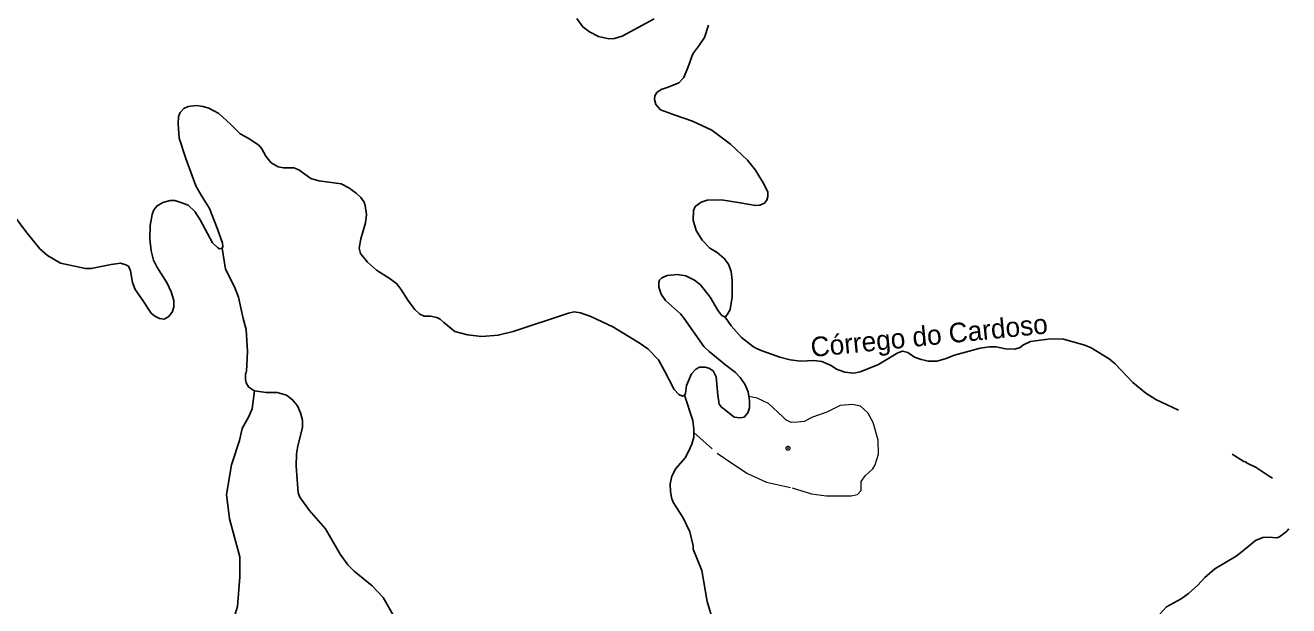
# Model space of a CAD drawing. Extents: x 396 to 422.2, y 7649.8 to 7677.6.
# Drawn here: x 403.57 to 408.72, y 7665.96 to 7668.32 of the extents above; entities that cross this region are included whole.
import ezdxf
from ezdxf.enums import TextEntityAlignment as Align

# ---------------------------------------------------------------- set-up
doc = ezdxf.new("R2010")
doc.units = 0
doc.header["$LTSCALE"] = 0.032
doc.header["$PDMODE"] = 32
doc.header["$PDSIZE"] = 0.016
doc.linetypes.add('SHORT_DASHED', pattern=[2.7, 1.5, -1.2])
for name, color, linetype, lineweight in [('2', 7, 'Continuous', 25), ('21', 7, 'SHORT_DASHED', 13), ('7', 7, 'Continuous', 25)]:
    doc.layers.add(name, color=color, linetype=linetype, lineweight=lineweight)
doc.layers.add('61', color=7, linetype='Continuous')

msp = doc.modelspace()

# ---------------------------------------------------------------- linework, layer by layer
at = {"layer": '2'}
for points in [[(405.8191, 7668.3498), (405.8427, 7668.3153), (405.8702, 7668.2957), (405.9066, 7668.276), (405.9489, 7668.2672), (405.9715, 7668.2681), (406.003, 7668.278), (406.1328, 7668.3478)], [(406.355, 7668.3222), (406.3383, 7668.2721), (406.3157, 7668.2377), (406.2911, 7668.2062), (406.2714, 7668.1531), (406.2537, 7668.1088), (406.234, 7668.0872), (406.1908, 7668.0695), (406.1613, 7668.0607), (406.1446, 7668.0479), (406.1357, 7668.0351), (406.1347, 7668.0204), (406.1396, 7667.9997), (406.1593, 7667.9781), (406.2183, 7667.9564), (406.2901, 7667.9309), (406.3688, 7667.8955), (406.4445, 7667.8384), (406.5133, 7667.7726), (406.5189, 7667.7656), (406.5467, 7667.7313), (406.5811, 7667.6742), (406.5959, 7667.6428), (406.5959, 7667.6251), (406.592, 7667.6093), (406.5821, 7667.5975), (406.5634, 7667.5897), (406.5457, 7667.5877), (406.4838, 7667.5995), (406.4081, 7667.6113), (406.3491, 7667.6093), (406.3245, 7667.6015), (406.3009, 7667.5838), (406.293, 7667.568), (406.2921, 7667.5287), (406.3039, 7667.4864), (406.3284, 7667.4471)], [(406.2576, 7666.8148), (406.2488, 7666.8119), (406.234, 7666.8178), (406.2144, 7666.8384), (406.176, 7666.9141), (406.1505, 7666.9594), (406.1082, 7667.0036), (406.0728, 7667.0292), (405.9646, 7667.0941), (405.8751, 7667.1364), (405.8329, 7667.1511), (405.8073, 7667.155), (405.7847, 7667.1501), (405.5595, 7667.0754), (405.4985, 7667.0597), (405.4317, 7667.0538), (405.3737, 7667.0607), (405.3215, 7667.0744), (405.2773, 7667.1108), (405.2616, 7667.1246), (405.2488, 7667.1324), (405.2222, 7667.1373), (405.1967, 7667.1373), (405.179, 7667.1452), (405.1583, 7667.1649), (405.1328, 7667.1983), (405.1023, 7667.2475), (405.0856, 7667.2691), (405.058, 7667.2888), (405.003, 7667.3252), (404.9656, 7667.3576), (404.9381, 7667.392), (404.9322, 7667.4146), (404.939, 7667.452), (404.9577, 7667.5179), (404.9626, 7667.5513), (404.9567, 7667.5877), (404.9518, 7667.6015), (404.939, 7667.6201), (404.9194, 7667.6388), (404.8899, 7667.6605), (404.8584, 7667.6762), (404.7984, 7667.6841), (404.7679, 7667.688), (404.7355, 7667.6978), (404.6863, 7667.7332), (404.6657, 7667.7411), (404.6411, 7667.7411), (404.6244, 7667.7411), (404.6028, 7667.745), (404.5742, 7667.7617), (404.5526, 7667.7883), (404.5359, 7667.8188), (404.5241, 7667.8335), (404.4798, 7667.862), (404.4474, 7667.8797), (404.4081, 7667.9191), (404.3599, 7667.9623), (404.3205, 7667.984), (404.2969, 7667.9918), (404.2694, 7667.9958), (404.236, 7667.9918), (404.2183, 7667.983), (404.2026, 7667.9663), (404.1967, 7667.9505), (404.1947, 7667.921), (404.1986, 7667.862), (404.2262, 7667.7794), (404.2665, 7667.6683), (404.2891, 7667.63), (404.3225, 7667.5759), (404.354, 7667.4953), (404.3756, 7667.4343), (404.3766, 7667.4205), (404.3741, 7667.4147)], [(404.3741, 7667.4147), (404.3628, 7667.4117), (404.3559, 7667.4156), (404.3353, 7667.4363), (404.2842, 7667.5297), (404.2625, 7667.5631), (404.236, 7667.5887), (404.2094, 7667.5995), (404.1809, 7667.6083), (404.1622, 7667.6083), (404.1327, 7667.6005), (404.1091, 7667.5867), (404.0964, 7667.571), (404.0885, 7667.5513), (404.0816, 7667.5061), (404.0796, 7667.451), (404.0855, 7667.4028), (404.0944, 7667.3655), (404.1082, 7667.3379), (404.1495, 7667.2711), (404.1662, 7667.2357), (404.177, 7667.2013), (404.177, 7667.1747), (404.1721, 7667.156), (404.1563, 7667.1354), (404.1377, 7667.1256), (404.119, 7667.1275), (404.1003, 7667.1373), (404.0846, 7667.1491), (404.0462, 7667.2091), (404.0197, 7667.2465), (404.0088, 7667.274), (404.001, 7667.3222), (403.9921, 7667.3409), (403.9823, 7667.3468), (403.9597, 7667.3527), (403.9223, 7667.3478), (403.8407, 7667.3311), (403.8181, 7667.3311), (403.7158, 7667.3527), (403.6627, 7667.3842), (403.6322, 7667.4117), (403.5742, 7667.4815), (403.5192, 7667.5572)], [(406.3284, 7667.4471), (406.3599, 7667.4137), (406.3894, 7667.396), (406.4189, 7667.3724), (406.4366, 7667.3488), (406.4474, 7667.3193)], [(406.4223, 7667.1333), (406.4091, 7667.1393), (406.3943, 7667.159), (406.3619, 7667.215), (406.3216, 7667.2642), (406.297, 7667.2839), (406.2626, 7667.3016), (406.2291, 7667.3075), (406.1859, 7667.3035), (406.1642, 7667.2937), (406.1554, 7667.2839), (406.1524, 7667.276), (406.1524, 7667.2553), (406.1623, 7667.2268), (406.18, 7667.2013), (406.2409, 7667.1472), (406.2557, 7667.1275), (406.3353, 7667.0135), (406.3579, 7666.9928), (406.4248, 7666.9377), (406.4651, 7666.9082), (406.4838, 7666.8876), (406.5025, 7666.8601), (406.5162, 7666.8296), (406.5189, 7666.8102)], [(406.4474, 7667.3193), (406.4504, 7667.2819), (406.4504, 7667.216), (406.4435, 7667.1649), (406.4327, 7667.1452), (406.4223, 7667.1333)], [(406.5189, 7666.8102), (406.5212, 7666.7942), (406.5221, 7666.7637), (406.5143, 7666.744), (406.5005, 7666.7253), (406.4828, 7666.7234), (406.4592, 7666.7263), (406.4376, 7666.743), (406.4179, 7666.7588), (406.4071, 7666.7666), (406.3983, 7666.7794), (406.3924, 7666.8158), (406.3865, 7666.8896), (406.3737, 7666.9141), (406.356, 7666.925), (406.3412, 7666.9289), (406.3186, 7666.9289), (406.3029, 7666.922), (406.2852, 7666.9023), (406.2645, 7666.8542), (406.2606, 7666.8217), (406.2576, 7666.8148)]]:
    msp.add_lwpolyline(points, dxfattribs=at)
at = {"layer": '21'}
msp.add_lwpolyline([(406.2949, 7666.6632), (406.39, 7666.5789), (406.4541, 7666.5351), (406.5131, 7666.4963), (406.5906, 7666.4609), (406.6951, 7666.4373), (406.7744, 7666.4137), (406.8351, 7666.4053), (406.8924, 7666.4053), (406.9362, 7666.4053), (406.9615, 7666.4103), (406.9767, 7666.4272), (406.9767, 7666.4643), (406.9935, 7666.4879), (407.0087, 7666.5014), (407.0239, 7666.5148), (407.034, 7666.5317), (407.0475, 7666.5755), (407.0458, 7666.6328), (407.0256, 7666.7037), (407.0036, 7666.7441), (406.9733, 7666.7711), (406.9413, 7666.7778), (406.8907, 7666.7728), (406.8367, 7666.7458), (406.7777, 7666.7256), (406.744, 7666.7087), (406.717, 7666.7053), (406.6918, 7666.7037), (406.6698, 7666.7155), (406.658, 7666.7273), (406.599, 7666.7812), (406.5535, 7666.8031), (406.5189, 7666.8102)], dxfattribs=at)
msp.add_point((406.6783, 7666.5991), dxfattribs=at)
at = {"layer": '7'}
for points in [[(404.5056, 7666.8326), (404.5046, 7666.8327), (404.4819, 7666.849), (404.4722, 7666.8655), (404.4691, 7666.879), (404.469, 7666.9018), (404.4722, 7666.9075), (404.4726, 7666.9136), (404.4778, 7666.9929), (404.4722, 7667.0835), (404.4596, 7667.1274), (404.4401, 7667.215), (404.4237, 7667.257), (404.3871, 7667.3284), (404.3741, 7667.4147)], [(408.2683, 7666.754), (408.176, 7666.7979), (408.1362, 7666.8241), (408.083, 7666.8675), (408.0102, 7666.9429), (407.9869, 7666.9635), (407.9126, 7667.0077), (407.8875, 7667.0186), (407.8007, 7667.0437), (407.7469, 7667.0454), (407.6662, 7667.0341), (407.635, 7667.0187), (407.6236, 7667.0096), (407.6019, 7667.0022), (407.5637, 7667.0045), (407.5257, 7667.0125), (407.4992, 7667.0125), (407.4605, 7667.0068), (407.3567, 7666.9788), (407.3189, 7666.9629), (407.2845, 7666.9544), (407.2492, 7666.9545), (407.2329, 7666.9578), (407.2201, 7666.9603), (407.1942, 7666.9707), (407.1669, 7666.9886), (407.1451, 7666.994), (407.126, 7666.9876), (407.0436, 7666.9393), (406.973, 7666.9099), (406.9463, 7666.9055), (406.9097, 7666.9096), (406.8756, 7666.9218), (406.8544, 7666.9367), (406.8165, 7666.952), (406.7835, 7666.9571), (406.73, 7666.9536), (406.6873, 7666.9599), (406.6446, 7666.9702), (406.5689, 7666.9968), (406.5475, 7667.0074), (406.5385, 7667.0118), (406.4893, 7667.0506), (406.4473, 7667.098), (406.4223, 7667.1333)], [(404.3457, 7665.768), (404.3847, 7665.8169), (404.3856, 7665.8188), (404.4151, 7665.883), (404.4154, 7665.8837), (404.4371, 7665.9543), (404.4466, 7666.0751), (404.4466, 7666.1568), (404.4039, 7666.3118), (404.3917, 7666.4108), (404.4116, 7666.532), (404.4448, 7666.6314), (404.456, 7666.6792), (404.4827, 7666.7281), (404.4961, 7666.7597), (404.5056, 7666.8326)], [(405.0743, 7665.9128), (405.0293, 7665.9919), (404.9852, 7666.0385), (404.9111, 7666.0991), (404.8859, 7666.1245), (404.855, 7666.1672), (404.7948, 7666.271), (404.7286, 7666.3468), (404.6909, 7666.4005), (404.6843, 7666.4172), (404.6756, 7666.5262), (404.6772, 7666.5771), (404.6822, 7666.6096), (404.7017, 7666.684), (404.7018, 7666.7134), (404.6937, 7666.7429), (404.6807, 7666.7716), (404.661, 7666.7967), (404.6366, 7666.8161), (404.5982, 7666.8259), (404.5529, 7666.8261), (404.5056, 7666.8326)], [(406.2949, 7666.6632), (406.2948, 7666.6765), (406.2906, 7666.7121), (406.2576, 7666.8148)], [(406.3783, 7665.8806), (406.3495, 7665.975), (406.3272, 7666.1007), (406.2921, 7666.1883), (406.2919, 7666.2022), (406.2793, 7666.2589), (406.2516, 7666.316), (406.2123, 7666.3769), (406.2056, 7666.3926), (406.1995, 7666.422), (406.198, 7666.4539), (406.2058, 7666.4851), (406.2219, 7666.5172), (406.2604, 7666.5621), (406.2798, 7666.6008), (406.2871, 7666.6154), (406.2951, 7666.6446), (406.2949, 7666.6632)], [(408.4873, 7666.5748), (408.5354, 7666.5447), (408.5431, 7666.5436), (408.5462, 7666.5396), (408.5854, 7666.5206), (408.6379, 7666.4859), (408.6516, 7666.4769)], [(407.9564, 7665.6232), (407.9682, 7665.6489), (407.9742, 7665.6628), (407.9894, 7665.6789), (408.007, 7665.7019), (408.0317, 7665.7398), (408.0732, 7665.795), (408.1383, 7665.8536), (408.1747, 7665.9045), (408.2204, 7665.9526), (408.2789, 7665.9863), (408.3101, 7666.0077), (408.3478, 7666.0409), (408.3762, 7666.0725), (408.4164, 7666.1075), (408.5038, 7666.1602), (408.5275, 7666.1793), (408.5819, 7666.2234), (408.6128, 7666.2357), (408.635, 7666.2374), (408.6686, 7666.2342), (408.6801, 7666.2384), (408.7089, 7666.2603), (408.7176, 7666.2705)]]:
    msp.add_lwpolyline(points, dxfattribs=at)

# ---------------------------------------------------------------- texts
at = {"layer": '61'}
msp.add_text('Córrego do Cardoso', height=0.08, rotation=5.739, dxfattribs=at).set_placement((407.257, 7667.0189), align=Align.CENTER)

doc.saveas('drawing.dxf')
